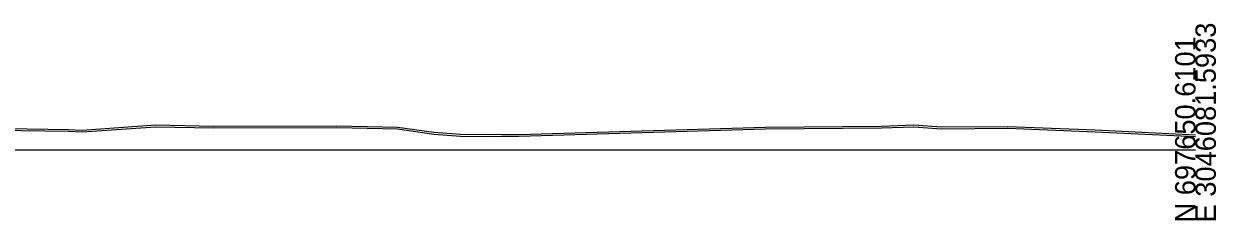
# Model space of a CAD drawing. Extents: x 1574 to 14903, y 7971 to 16537.
# Drawn here: x 4939.1 to 5102.8, y 10990.3 to 11017.3 of the extents above; entities that cross this region are included whole.
import ezdxf

# ---------------------------------------------------------------- set-up
doc = ezdxf.new("R2010")
doc.units = 0
for name, color, linetype in [('DESIGN - SHEET - Light Grid', 7, 'Continuous'), ('SURVEY - GROUND - Bottom of Topsoil Layer', 7, 'Continuous'), ('SURVEY - GROUND - Top of Ground', 7, 'Continuous')]:
    doc.layers.add(name, color=color, linetype=linetype)

msp = doc.modelspace()

# ---------------------------------------------------------------- linework, layer by layer
at = {"layer": 'DESIGN - SHEET - Light Grid'}
msp.add_line((4800, 11000), (5100, 11000), dxfattribs=at)
at = {"layer": 'SURVEY - GROUND - Bottom of Topsoil Layer'}
for p, q in [((4911.06, 11003.1), (4945.23, 11002.53)), ((4945.23, 11002.53), (4947.14, 11002.46)), ((4947.14, 11002.46), (4957.21, 11003.16)), ((4957.21, 11003.16), (4965.22, 11002.99)), ((4965.22, 11002.99), (4982.08, 11003.05)), ((4982.08, 11003.05), (4990.43, 11002.87)), ((4990.43, 11002.87), (4995.4, 11002.15)), ((5007.1, 11001.85), (5040.97, 11002.87)), ((5040.97, 11002.87), (5056.87, 11002.99)), ((5056.87, 11002.99), (5061.34, 11003.16)), ((5061.34, 11003.16), (5065.11, 11002.89)), ((5065.11, 11002.89), (5074.24, 11002.96)), ((5074.24, 11002.96), (5086.22, 11002.47)), ((5086.22, 11002.47), (5100, 11001.81)), ((4995.4, 11002.15), (4999.08, 11001.87)), ((4999.08, 11001.87), (5003.62, 11001.84)), ((5003.62, 11001.84), (5004.72, 11001.87)), ((5004.72, 11001.87), (5007.1, 11001.85))]:
    msp.add_line(p, q, dxfattribs=at)
at = {"layer": 'SURVEY - GROUND - Top of Ground'}
msp.add_lwpolyline([(4911.06, 11003.35), (4945.23, 11002.78), (4947.14, 11002.71), (4957.21, 11003.41), (4965.22, 11003.24), (4982.08, 11003.3), (4990.43, 11003.12), (4995.4, 11002.4), (4999.08, 11002.12), (5003.62, 11002.09), (5004.72, 11002.12), (5007.1, 11002.1), (5040.97, 11003.12), (5056.87, 11003.24), (5061.34, 11003.41), (5065.11, 11003.14), (5074.24, 11003.21), (5086.22, 11002.72), (5100, 11002.06)], dxfattribs=at)

# ---------------------------------------------------------------- texts
at = {"layer": 'DESIGN - SHEET - Light Grid'}
for s, p in [('E 3046081.5933', (5102.8, 10990)), ('N 697650.6101', (5100, 10990))]:
    msp.add_text(s, height=2.8, rotation=90, dxfattribs=at).set_placement(p)

doc.saveas('drawing.dxf')
